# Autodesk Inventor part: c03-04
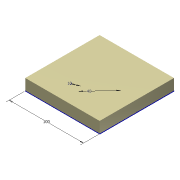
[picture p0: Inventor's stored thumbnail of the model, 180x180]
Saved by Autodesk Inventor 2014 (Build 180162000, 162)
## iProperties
Created: 2011-11
Part Number: c03-04
Material: Iron, Cast
Document SubType Name: Modeling
Designer: Thom Tremblay
Density: 7.25 g/cm^3
Mass: 1087.5 g
Surface Area: 260 cm^2
Volume: 150 cm^3
Appearance: Nylon 6
Author: Thom Tremblay
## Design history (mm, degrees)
sketch "Sketch1"
  geometry: L1 (50, -50)-(-50, -50); L2 (-50, -50)-(-50, 50); L3 (-50, 50)-(50, 50); L4 (50, 50)-(50, -50); C1 r 20 at (0, 0); C2 r 30 at (0, 0); 3 further points
  constraints: 8 end point, 2 centre point, 2 coincident, 2 midpoint, 2 parallel, 2 perpendicular, 1 horizontal, 1 horizontal alignment, 1 vertical alignment
  dimensions: "d0" = 100 distance of L2.end L3.end; "d3" = 40 diameter of C1; "d4" = 10 radial gap between concentric circles of C2 C1
extrude "Extrusion1" new body sketch "Sketch1" distance "d1" = 15; taper "d2" = 0 deg
body "Solid1"
